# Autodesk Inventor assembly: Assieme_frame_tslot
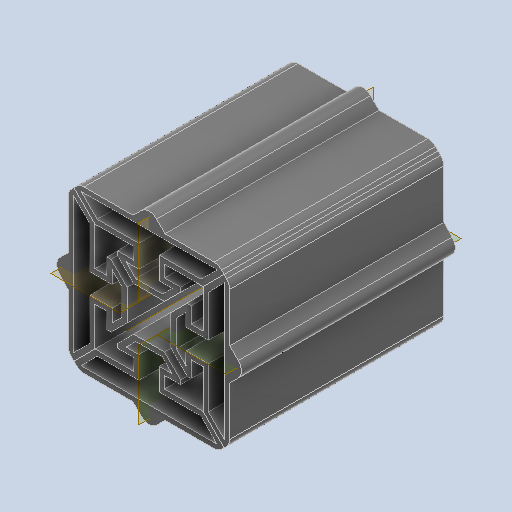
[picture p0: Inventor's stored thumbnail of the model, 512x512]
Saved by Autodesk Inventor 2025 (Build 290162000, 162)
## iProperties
Created: 2026-03
Part Number: Assieme_frame_tslot
Document SubType Name: Assembly
Designer: R5800u
Author: R5800u
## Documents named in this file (2)
- C:\Users\Ryzen5700u\Desktop\robot_cicloidale_singolo\Workgroups\NotInProject\Assieme_frame_tslot.iam
- C:\Users\Ryzen5700u\Desktop\robot_cicloidale_singolo\Workgroups\NotInProject\frame_tslot.ipt
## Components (4 placed, 1 different names)
1. frame_tslot:1
2. frame_tslot:2
3. frame_tslot:3
4. frame_tslot:4
